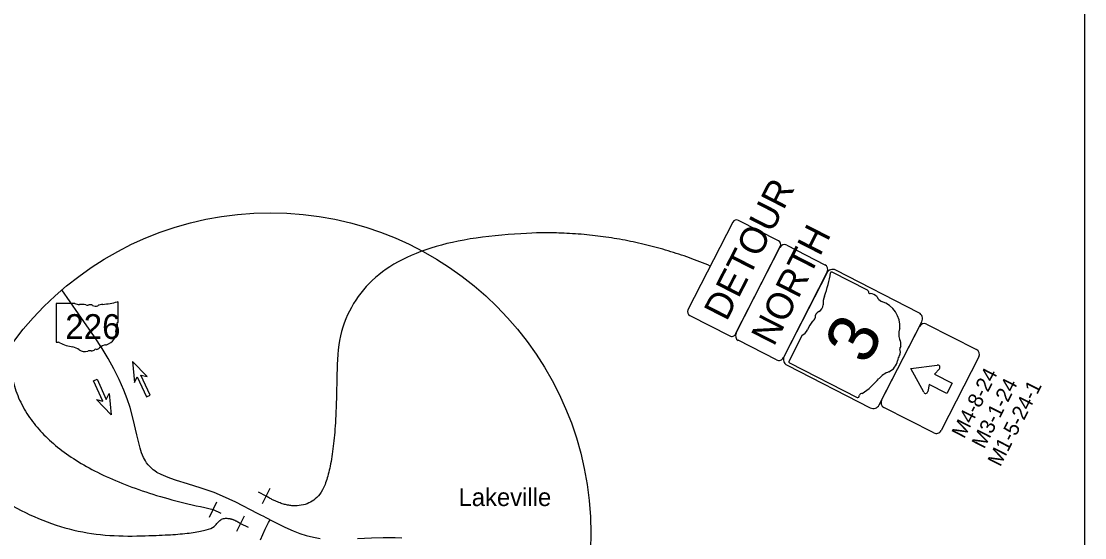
# Model space of a CAD drawing. Extents: x -15.3 to 34, y 0 to 22.
# Drawn here: x 6.79 to 16.75, y 5.71 to 10.54 of the extents above; entities that cross this region are included whole.
import ezdxf

# ---------------------------------------------------------------- set-up
doc = ezdxf.new("R2010")
doc.units = 0
for name, color, linetype in [('GM_X_State_Route', 7, 'Continuous'), ('GM_X_State_Shield', 7, 'Continuous'), ('GM_X_Unincorporated_Text', 7, 'Continuous'), ('PM_P_Cells', 7, 'Continuous'), ('SC_Scratch1', 7, 'Continuous'), ('SH_Text', 7, 'Continuous'), ('SN_P_Signs', 7, 'Continuous')]:
    doc.layers.add(name, color=color, linetype=linetype)

msp = doc.modelspace()

# ---------------------------------------------------------------- linework, layer by layer
at = {"layer": 'GM_X_State_Route'}
for points in [[(9.031, 5.6885), (9.0753, 5.7873), (9.0885, 5.8127), (9.108, 5.8485), (9.1237, 5.8737), (9.0844, 5.894), (9.0628, 5.9049), (9.0342, 5.9193), (9.0041, 5.9343), (8.7996, 6.0389), (8.6773, 6.0971), (8.597, 6.1305), (8.478, 6.1717), (8.3493, 6.2122), (8.2454, 6.2442), (8.1846, 6.2645), (8.1448, 6.2795), (8.1016, 6.2979), (8.0618, 6.3194), (8.0421, 6.3322), (8.0271, 6.3437), (8.0109, 6.3577), (7.9945, 6.3737), (7.9794, 6.39), (7.9657, 6.4077), (7.9539, 6.4259), (7.9357, 6.4595), (7.9187, 6.5031), (7.9056, 6.5452), (7.8755, 6.6714), (7.8396, 6.8184), (7.8113, 6.925), (7.7832, 7.0078), (7.7513, 7.0895), (7.7072, 7.1898), (7.6585, 7.2882), (7.6058, 7.3846), (7.5489, 7.4783), (7.477, 7.5881), (7.3279, 7.8042), (7.1719, 8.0271)], [(9.1237, 5.8737), (9.2584, 5.8068), (9.3383, 5.7718), (9.3997, 5.7477), (9.4608, 5.7282), (9.5285, 5.7119), (9.5908, 5.701)], [(9.9419, 5.7016), (10.0728, 5.7075), (10.1819, 5.7106), (10.2933, 5.7107), (10.3558, 5.7064)]]:
    msp.add_lwpolyline(points, dxfattribs=at)
at = {"layer": 'GM_X_State_Shield'}
for p, q in [((7.1189, 7.8955), (7.1189, 7.5433)), ((7.2945, 7.9016), (7.1246, 7.9016)), ((7.6989, 7.7261), (7.6989, 7.9103)), ((7.6989, 7.7261), (7.6989, 7.7261))]:
    msp.add_line(p, q, dxfattribs=at)
for centre, major_axis, start_param, end_param in [((7.1255, 7.8963), (0.00672, 0), 1.712693, 3.28349), ((7.3349, 7.9425), (0.0652, 0), 4.042523, 4.731795), ((7.3565, 7.7039), (0.234, 0), 1.404758, 1.657858), ((7.4096, 7.8981), (0.0188, 0), 3.836095, 5.185415), ((7.4372, 7.8574), (0.0391, 0), 0.950623, 2.079405), ((7.4877, 7.9132), (0.047, 0), 4.081561, 5.145723), ((7.5708, 7.794), (0.1238, 0), 1.699011, 2.107814), ((7.4923, 8.3818), (0.6152, 0), 4.814394, 5.042369), ((7.6925, 7.9111), (0.00646, 0), 6.141152, 7.989035), ((7.7221, 7.649), (0.0436, 0), 2.387724, 3.262537), ((7.6974, 7.7126), (0.00999, 0), 1.883978, 3.671073), ((7.6339, 7.6893), (0.06, 0), 5.934695, 6.695948), ((7.692, 7.7254), (0.00691, 0), 5.05454, 6.418171), ((7.5268, 7.6255), (0.1539, 0), 5.101752, 6.440018), ((7.1256, 7.5426), (0.00678, 0), 3.00124, 4.508301), ((7.1266, 7.5786), (0.0517, 0), 4.665946, 4.897461), ((7.1372, 7.523), (0.0187, 0), 0.519207, 1.627899), ((7.3727, 7.8395), (0.4442, 0), 4.195997, 4.488961), ((7.2403, 7.3851), (0.139, 0), 0.823519, 1.323587), ((7.448, 7.4949), (0.047, 0), 4.691044, 5.507374), ((7.4905, 7.4608), (0.0132, 0), 1.147584, 2.315152), ((7.4849, 7.5092), (0.0497, 0), 4.937069, 5.64225), ((7.5916, 7.4445), (0.0843, 0), 1.647645, 2.488434), ((7.3906, 7.5213), (0.0882, 0), 4.026481, 4.996735), ((7.4416, 7.3995), (0.0725, 0), 1.495662, 1.94098)]:
    msp.add_ellipse(centre, major_axis=major_axis, ratio=0.8, start_param=start_param, end_param=end_param, dxfattribs=at)
at = {"layer": 'PM_P_Cells'}
for p, q in [((7.8329, 7.3586), (7.8329, 7.3586)), ((7.8329, 7.3586), (7.8516, 7.161)), ((7.97, 7.2152), (7.8329, 7.3586)), ((7.4686, 7.1749), (7.5027, 7.1905)), ((7.5543, 6.9873), (7.4686, 7.1749)), ((7.4856, 7.1827), (7.4856, 7.1827)), ((7.5027, 7.1905), (7.5884, 7.0029)), ((7.8516, 7.161), (7.8782, 7.2144)), ((7.8782, 7.2144), (7.9639, 7.0268)), ((7.998, 7.0424), (7.9123, 7.23)), ((7.9123, 7.23), (7.97, 7.2152)), ((7.6337, 6.8587), (7.4966, 7.0021)), ((7.4966, 7.0021), (7.5543, 6.9873)), ((7.5884, 7.0029), (7.615, 7.0563)), ((7.615, 7.0563), (7.6337, 6.8587)), ((7.9639, 7.0268), (7.998, 7.0424)), ((7.981, 7.0346), (7.981, 7.0346)), ((7.6337, 6.8587), (7.6337, 6.8587))]:
    msp.add_line(p, q, dxfattribs=at)
at = {"layer": 'SH_Text'}
msp.add_line((16.75, 0.5), (16.75, 21.5), dxfattribs=at)
msp.add_circle((9.125, 5.75), 3, dxfattribs=at)
for points in [[(5.6459, 8.6155), (6.5309, 8.1591), (6.8691, 6.3222), (8.5889, 5.9722)], [(13.2442, 8.2509), (12.1616, 8.7036), (9.7469, 8.2889), (9.7469, 6.2585), (9.3803, 5.918), (9.0841, 6.0971)], [(5.1236, 7.3616), (5.4881, 6.9711), (6.9531, 5.7245), (8.5534, 5.7245), (8.6877, 5.943), (8.8454, 5.8401)]]:
    msp.add_open_spline(points, degree=2, dxfattribs=at)
at = {"layer": 'SN_P_Signs'}
for p, q in [((13.4845, 7.6226), (13.8943, 8.4239)), ((13.9616, 8.4457), (14.3177, 8.2635)), ((14.3395, 8.1963), (13.9297, 7.3949)), ((14.7166, 8.0237), (14.3852, 8.1931)), ((14.7165, 8.0236), (14.7166, 8.0237)), ((14.8485, 6.9953), (15.2014, 7.6853)), ((15.2686, 7.7071), (15.7361, 7.4681)), ((14.1033, 7.6031), (13.9783, 7.3586)), ((13.8624, 7.3732), (13.5063, 7.5553)), ((15.7578, 7.4008), (15.405, 6.7108)), ((13.985, 7.3448), (14.6185, 7.0209)), ((15.1224, 7.2905), (15.3676, 7.3221)), ((15.2419, 7.0697), (15.1224, 7.2905)), ((15.389, 7.2877), (15.342, 7.2396)), ((15.342, 7.2396), (15.509, 7.1542)), ((15.2922, 7.1422), (15.2808, 7.0761)), ((15.4591, 7.0568), (15.2922, 7.1422)), ((15.509, 7.1542), (15.4591, 7.0568)), ((15.3377, 6.689), (14.8703, 6.928)), ((9.0841, 6.0971), (9.0129, 6.1335)), ((9.1205, 6.1683), (9.0477, 6.0259)), ((8.5537, 5.9004), (8.6242, 6.044)), ((8.5889, 5.9722), (8.6608, 5.937)), ((8.8102, 5.7683), (8.8807, 5.9119)), ((8.8454, 5.8401), (8.9172, 5.8049))]:
    msp.add_line(p, q, dxfattribs=at)
for points in [[(13.8814, 8.4866), (13.5075, 8.6778)], [(13.4537, 8.6604), (13.0348, 7.8413)], [(13.48, 7.6137), (13.8988, 8.4328)], [(14.3338, 8.1851), (13.9354, 7.4061)], [(15.1969, 7.814), (14.4179, 8.2123)], [(13.0522, 7.7875), (13.4262, 7.5963)], [(14.8258, 6.9508), (15.2241, 7.7299)], [(13.9626, 7.322), (14.7417, 6.9236)]]:
    msp.add_lwpolyline(points, dxfattribs=at)
for centre, radius, start, end in [((13.4893, 8.6422), 0.04, 62.91777, 152.91777), ((13.8632, 8.451), 0.04, 332.91777, 62.91777), ((13.9388, 8.4011), 0.05, 62.91777, 152.91777), ((13.3852, 8.3294), 0.9942, 338.76224, 351.82423), ((14.295, 8.219), 0.05, 332.91777, 62.91777), ((14.3894, 8.1567), 0.0625, 62.91777, 152.91777), ((14.3791, 8.1846), 0.0104, 54.77986, 160.65577), ((14.5001, 7.9017), 0.2, 160.26395, 183.68663), ((14.7128, 8.0131), 0.0112, 352.52158, 70.6519), ((14.7399, 8.0091), 0.0162, 170.86176, 273.25474), ((14.735, 7.8962), 0.097, 42.95074, 86.56734), ((14.2246, 7.8918), 0.076, 296.77398, 357.74597), ((14.8723, 7.986), 0.0705, 199.72427, 249.84737), ((14.7708, 7.6834), 0.2487, 355.22666, 71.90361), ((13.0704, 7.8231), 0.04, 152.91777, 242.91777), ((14.2879, 7.7679), 0.0632, 117.38446, 182.0589), ((15.1685, 7.7583), 0.0625, 332.91777, 62.91777), ((14.5047, 7.5105), 0.3782, 143.40447, 157.90604), ((14.1943, 7.7656), 0.0304, 282.70983, 0.02014), ((15.2459, 7.6626), 0.05, 62.91777, 152.91777), ((13.4444, 7.6319), 0.04, 242.91777, 332.91777), ((13.5291, 7.5998), 0.05, 152.91777, 242.91777), ((14.0595, 7.6989), 0.1053, 294.53728, 334.02966), ((15.1443, 7.6102), 0.1362, 157.3209, 205.49452), ((14.9479, 7.4499), 0.0759, 331.69479, 18.46705), ((15.0405, 7.4797), 0.0214, 128.6695, 195.5662), ((14.9493, 7.5161), 0.0803, 345.79097, 26.19488), ((13.8852, 7.4177), 0.05, 242.91777, 332.91777), ((13.9911, 7.3776), 0.0625, 152.91777, 242.91777), ((15.1147, 7.3529), 0.1171, 148.6129, 174.12772), ((15.7133, 7.4236), 0.05, 332.91777, 62.91777), ((13.9886, 7.3551), 0.0109, 161.04788, 251.04788), ((14.8582, 7.3916), 0.1425, 293.61815, 349.20961), ((15.374, 7.3022), 0.0208, 315.71317, 107.92733), ((14.2727, 7.6585), 0.7179, 303.3307, 320.11627), ((14.9925, 7.05), 0.2246, 110.10193, 138.75375), ((15.2602, 7.0796), 0.0208, 208.32899, 350.12238), ((14.6249, 7.0298), 0.011, 234.87616, 321.22439), ((14.5608, 7.0644), 0.0836, 330.25677, 343.52163), ((14.6686, 7.0285), 0.0302, 92.66615, 156.18952), ((14.893, 6.9726), 0.05, 152.91777, 242.91777), ((14.7701, 6.9793), 0.0625, 242.91777, 332.91777), ((15.3605, 6.7336), 0.05, 242.91777, 332.91777)]:
    msp.add_arc(centre, radius, start, end, dxfattribs=at)

# ---------------------------------------------------------------- texts
at = {"layer": 'GM_X_State_Shield'}
msp.add_text('226', height=0.23203, dxfattribs=at).set_placement((7.2039, 7.5682))
at = {"layer": 'GM_X_Unincorporated_Text'}
msp.add_text('Lakeville', height=0.1668, rotation=0.00001, dxfattribs=at).set_placement((10.8866, 6.0039))
at = {"layer": 'SC_Scratch1'}
for s, p in [('M4-8-24', (15.6211, 6.628)), ('M3-1-24', (15.8081, 6.5324)), ('M1-5-24-1', (15.9584, 6.365))]:
    msp.add_text(s, height=0.14, rotation=62.91777, dxfattribs=at).set_placement(p)
at = {"layer": 'SN_P_Signs'}
for s, height, p in [('DETOUR', 0.25, (13.3967, 7.7254)), ('NORTH', 0.25, (13.8382, 7.4905)), ('3', 0.4688, (14.7115, 7.3128))]:
    msp.add_text(s, height=height, rotation=62.91777, dxfattribs=at).set_placement(p)

doc.saveas('drawing.dxf')
